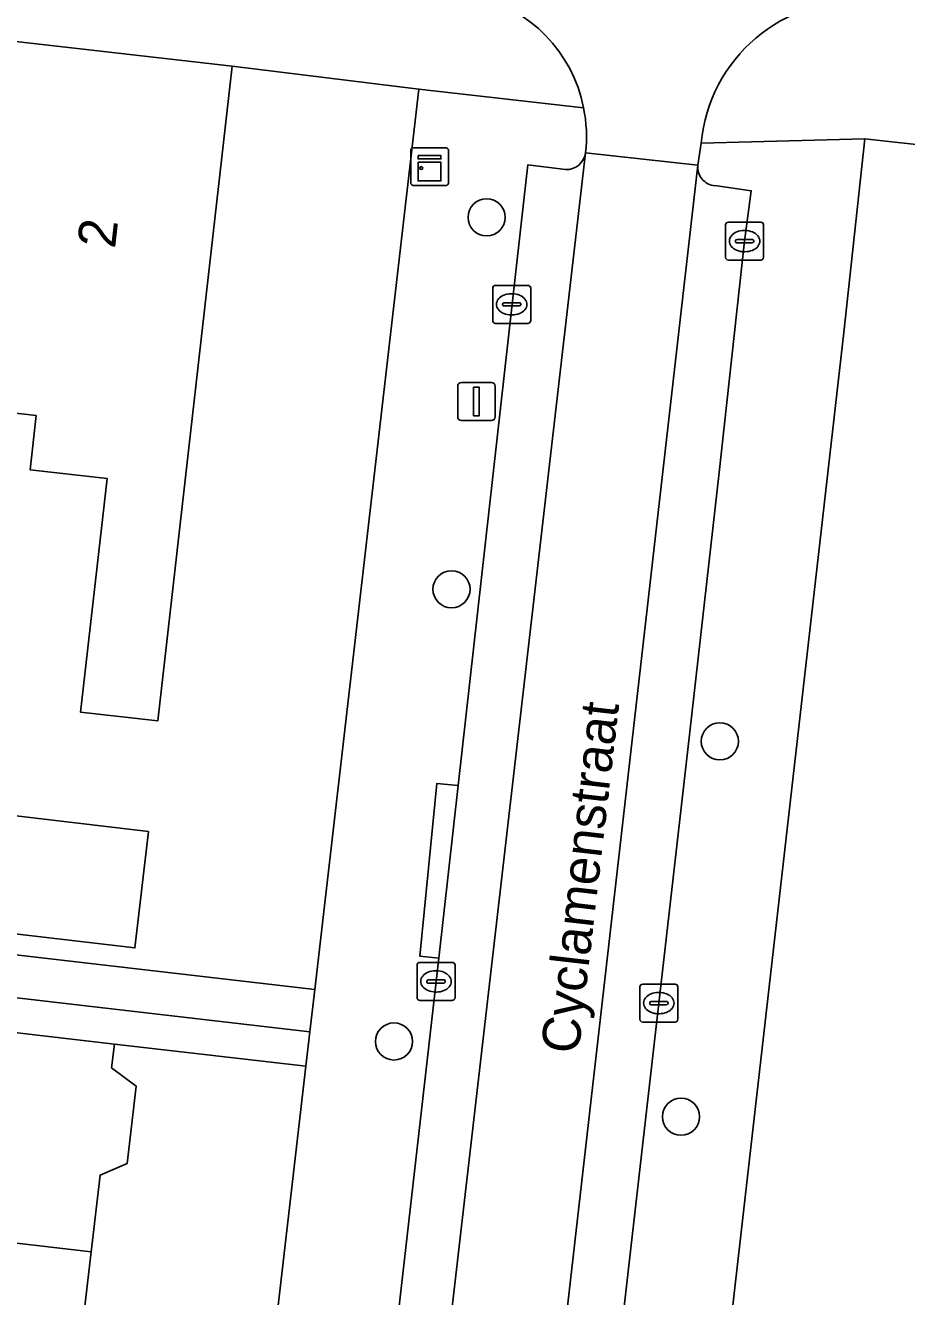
# Model space of a CAD drawing. Extents: x 161692 to 162379, y 380760 to 381678.
# Drawn here: x 162142.95 to 162166.16, y 381103.96 to 381137.43 of the extents above; entities that cross this region are included whole.
import ezdxf

# ---------------------------------------------------------------- set-up
doc = ezdxf.new("R2010")
doc.units = 0
for name, color, linetype in [('IMGEO_Boom', 7, 'Continuous'), ('IMGEO_Erf', 7, 'Continuous'), ('IMGEO_Kast', 7, 'Continuous'), ('IMGEO_Kolk', 7, 'Continuous'), ('IMGEO_Lichtmast', 7, 'Continuous'), ('IMGEO_Openbare_ruimte_label', 7, 'Continuous'), ('IMGEO_Pand', 7, 'Continuous'), ('IMGEO_Pand_nummerreeks', 7, 'Continuous'), ('IMGEO_Parkeervlak_open', 7, 'Continuous'), ('IMGEO_Rijbaan_lokaal_open', 7, 'Continuous'), ('IMGEO_Voetpad_open', 7, 'Continuous')]:
    doc.layers.add(name, color=color, linetype=linetype)

msp = doc.modelspace()

# ---------------------------------------------------------------- linework, layer by layer
at = {"layer": 'IMGEO_Boom'}
for centre in [(162155.095, 381132.374), (162154.17, 381122.581), (162161.239, 381118.576), (162152.655, 381110.673), (162160.215, 381108.691)]:
    msp.add_circle(centre, 0.489, dxfattribs=at)
at = {"layer": 'IMGEO_Erf'}
for points in [[(162104.656, 381117.359), (162150.568, 381112.043), (162153.313, 381135.753), (162148.389, 381136.356), (162146.43, 381119.113), (162144.4, 381119.344), (162145.098, 381125.495), (162143.069, 381125.726), (162143.231, 381127.155), (162140.973, 381127.411)], [(162171.096, 381133.774), (162165.058, 381134.446), (162164.506, 381129.345), (162160.903, 381097.801)], [(162140.287, 381068.173), (162145.42, 381067.579), (162150.334, 381110.022), (162145.291, 381110.606), (162145.217, 381109.977), (162145.862, 381109.497), (162145.625, 381107.462), (162144.913, 381107.155), (162144.677, 381105.13), (162144.441, 381103.106), (162145.069, 381102.638), (162144.826, 381100.55), (162144.087, 381100.231), (162144.046, 381099.885), (162144.006, 381099.539), (162144.651, 381099.059), (162144.403, 381096.929), (162143.679, 381096.788), (162143.437, 381094.71), (162143.194, 381092.63), (162143.859, 381092.136), (162143.6, 381089.916), (162142.846, 381089.59)]]:
    msp.add_lwpolyline(points, dxfattribs=at)
msp.add_lwpolyline([(162146.19, 381116.206), (162145.832, 381113.136), (162139.734, 381113.847), (162140.092, 381116.918)], close=True, dxfattribs=at)
at = {"layer": 'IMGEO_Kast'}
for p, q in [((162153.095, 381133.284), (162153.095, 381134.125)), ((162153.095, 381134.125), (162153.095, 381133.284)), ((162153.17, 381134.209), (162154.011, 381134.209)), ((162154.011, 381134.209), (162153.17, 381134.209)), ((162154.095, 381134.134), (162154.095, 381133.293)), ((162154.095, 381133.293), (162154.095, 381134.134)), ((162154.02, 381133.209), (162153.179, 381133.209)), ((162153.179, 381133.209), (162154.02, 381133.209))]:
    msp.add_line(p, q, dxfattribs=at)
for points in [[(162153.29, 381133.999), (162153.89, 381133.999), (162153.89, 381133.914), (162153.29, 381133.914), (162153.29, 381133.999)], [(162153.29, 381133.824), (162153.89, 381133.824), (162153.89, 381133.335), (162153.29, 381133.335), (162153.29, 381133.824)]]:
    msp.add_lwpolyline(points, dxfattribs=at)
msp.add_circle((162153.374, 381133.673), 0.0377, dxfattribs=at)
for centre, start, end in [((162153.173, 381134.131), 92.4484, 184.2845), ((162153.173, 381134.131), 92.4484, 184.2845), ((162154.017, 381134.131), 2.4484, 94.2845), ((162154.017, 381134.131), 2.4484, 94.2845), ((162153.173, 381133.287), 182.4484, 274.2845), ((162153.173, 381133.287), 182.4484, 274.2845), ((162154.017, 381133.287), 272.4484, 4.2845), ((162154.017, 381133.287), 272.4484, 4.2845)]:
    msp.add_arc(centre, 0.0779, start, end, dxfattribs=at)
at = {"layer": 'IMGEO_Kolk'}
for p, q in [((162161.465, 381132.248), (162162.317, 381132.248)), ((162161.39, 381131.322), (162161.39, 381132.174)), ((162161.878, 381132.028), (162161.903, 381132.028)), ((162162.391, 381132.174), (162162.391, 381131.322)), ((162161.649, 381131.742), (162161.649, 381131.754)), ((162162.087, 381131.705), (162161.689, 381131.705)), ((162161.692, 381131.791), (162162.09, 381131.791)), ((162162.133, 381131.754), (162162.133, 381131.742)), ((162162.317, 381131.248), (162161.465, 381131.248)), ((162161.901, 381131.468), (162161.876, 381131.468)), ((162155.331, 381130.583), (162156.183, 381130.583)), ((162155.256, 381129.657), (162155.256, 381130.509)), ((162155.744, 381130.363), (162155.769, 381130.363)), ((162156.257, 381130.509), (162156.257, 381129.657)), ((162155.515, 381130.077), (162155.515, 381130.089)), ((162155.953, 381130.04), (162155.555, 381130.04)), ((162155.558, 381130.126), (162155.956, 381130.126)), ((162155.999, 381130.089), (162155.999, 381130.077)), ((162156.183, 381129.583), (162155.331, 381129.583)), ((162155.767, 381129.803), (162155.742, 381129.803)), ((162153.262, 381111.828), (162153.262, 381112.68)), ((162153.337, 381112.754), (162154.189, 381112.754)), ((162153.75, 381112.534), (162153.775, 381112.534)), ((162154.263, 381112.68), (162154.263, 381111.828)), ((162153.521, 381112.248), (162153.521, 381112.26)), ((162153.959, 381112.211), (162153.561, 381112.211)), ((162153.564, 381112.297), (162153.962, 381112.297)), ((162154.005, 381112.26), (162154.005, 381112.248)), ((162159.207, 381112.183), (162160.059, 381112.183)), ((162153.773, 381111.974), (162153.748, 381111.974)), ((162159.132, 381111.257), (162159.132, 381112.109)), ((162159.62, 381111.963), (162159.645, 381111.963)), ((162160.133, 381112.109), (162160.133, 381111.257)), ((162154.189, 381111.754), (162153.337, 381111.754)), ((162159.391, 381111.677), (162159.391, 381111.689)), ((162159.829, 381111.64), (162159.431, 381111.64)), ((162159.434, 381111.726), (162159.832, 381111.726)), ((162159.875, 381111.689), (162159.875, 381111.677)), ((162160.059, 381111.183), (162159.207, 381111.183)), ((162159.643, 381111.403), (162159.618, 381111.403))]:
    msp.add_line(p, q, dxfattribs=at)
for points in [[(162161.465, 381132.248), (162162.317, 381132.248)], [(162161.39, 381131.322), (162161.39, 381132.174)], [(162162.391, 381132.174), (162162.391, 381131.322)], [(162162.317, 381131.248), (162161.465, 381131.248)], [(162155.331, 381130.583), (162156.183, 381130.583)], [(162155.256, 381129.657), (162155.256, 381130.509)], [(162156.257, 381130.509), (162156.257, 381129.657)], [(162156.183, 381129.583), (162155.331, 381129.583)], [(162153.262, 381111.828), (162153.262, 381112.68)], [(162153.337, 381112.754), (162154.189, 381112.754)], [(162154.263, 381112.68), (162154.263, 381111.828)], [(162159.207, 381112.183), (162160.059, 381112.183)], [(162159.132, 381111.257), (162159.132, 381112.109)], [(162160.133, 381112.109), (162160.133, 381111.257)], [(162154.189, 381111.754), (162153.337, 381111.754)], [(162160.059, 381111.183), (162159.207, 381111.183)]]:
    msp.add_lwpolyline(points, dxfattribs=at)
for centre, radius, start, end in [((162161.467, 381132.172), 0.0765, 91.552, 178.448), ((162161.467, 381132.172), 0.0765, 91.552, 178.448), ((162162.315, 381132.172), 0.0765, 1.552, 88.448), ((162162.315, 381132.172), 0.0765, 1.552, 88.448), ((162161.689, 381131.751), 0.0403, 85.8775, 175.7526), ((162161.686, 381131.741), 0.0366, 178.938, 274.7102), ((162162.09, 381131.748), 0.043, 264.8664, 352.4533), ((162162.094, 381131.753), 0.0386, 1.7309, 96.639), ((162161.467, 381131.324), 0.0765, 181.552, 268.448), ((162161.467, 381131.324), 0.0765, 181.552, 268.448), ((162162.315, 381131.324), 0.0765, 271.552, 358.448), ((162162.315, 381131.324), 0.0765, 271.552, 358.448), ((162155.333, 381130.507), 0.0765, 91.552, 178.448), ((162155.333, 381130.507), 0.0765, 91.552, 178.448), ((162156.181, 381130.507), 0.0765, 1.552, 88.448), ((162156.181, 381130.507), 0.0765, 1.552, 88.448), ((162155.555, 381130.086), 0.0403, 85.8775, 175.7526), ((162155.552, 381130.076), 0.0366, 178.938, 274.7102), ((162155.956, 381130.083), 0.043, 264.8664, 352.4533), ((162155.96, 381130.088), 0.0386, 1.7309, 96.639), ((162155.333, 381129.659), 0.0765, 181.552, 268.448), ((162155.333, 381129.659), 0.0765, 181.552, 268.448), ((162156.181, 381129.659), 0.0765, 271.552, 358.448), ((162156.181, 381129.659), 0.0765, 271.552, 358.448), ((162153.339, 381112.678), 0.0765, 91.552, 178.448), ((162153.339, 381112.678), 0.0765, 91.552, 178.448), ((162154.187, 381112.678), 0.0765, 1.552, 88.448), ((162154.187, 381112.678), 0.0765, 1.552, 88.448), ((162153.561, 381112.257), 0.0403, 85.8775, 175.7526), ((162153.558, 381112.247), 0.0366, 178.938, 274.7102), ((162153.962, 381112.254), 0.043, 264.8664, 352.4533), ((162153.966, 381112.259), 0.0386, 1.7309, 96.639), ((162159.209, 381112.107), 0.0765, 91.552, 178.448), ((162159.209, 381112.107), 0.0765, 91.552, 178.448), ((162160.057, 381112.107), 0.0765, 1.552, 88.448), ((162160.057, 381112.107), 0.0765, 1.552, 88.448), ((162153.339, 381111.83), 0.0765, 181.552, 268.448), ((162153.339, 381111.83), 0.0765, 181.552, 268.448), ((162154.187, 381111.83), 0.0765, 271.552, 358.448), ((162154.187, 381111.83), 0.0765, 271.552, 358.448), ((162159.431, 381111.686), 0.0403, 85.8775, 175.7526), ((162159.428, 381111.676), 0.0366, 178.938, 274.7102), ((162159.832, 381111.683), 0.043, 264.8664, 352.4533), ((162159.836, 381111.688), 0.0386, 1.7309, 96.639), ((162159.209, 381111.259), 0.0765, 181.552, 268.448), ((162159.209, 381111.259), 0.0765, 181.552, 268.448), ((162160.057, 381111.259), 0.0765, 271.552, 358.448), ((162160.057, 381111.259), 0.0765, 271.552, 358.448)]:
    msp.add_arc(centre, radius, start, end, dxfattribs=at)
for centre, major_axis, ratio, start_param, end_param in [((162161.877, 381131.748), (-0.387, 0.002), 0.722429, 4.712389, 7.853982), ((162161.902, 381131.748), (-0.39, 0.002), 0.717154, 1.570796, 4.712389), ((162155.743, 381130.083), (-0.387, 0.002), 0.722429, 4.712389, 7.853982), ((162155.768, 381130.083), (-0.39, 0.002), 0.717154, 1.570796, 4.712389), ((162153.749, 381112.254), (-0.387, 0.002), 0.722429, 4.712389, 7.853982), ((162153.774, 381112.254), (-0.39, 0.002), 0.717154, 1.570796, 4.712389), ((162159.619, 381111.683), (-0.387, 0.002), 0.722429, 4.712389, 7.853982), ((162159.644, 381111.683), (-0.39, 0.002), 0.717154, 1.570796, 4.712389)]:
    msp.add_ellipse(centre, major_axis=major_axis, ratio=ratio, start_param=start_param, end_param=end_param, dxfattribs=at)
at = {"layer": 'IMGEO_Lichtmast'}
for p, q in [((162154.333, 381127.125), (162154.333, 381127.925)), ((162154.333, 381127.925), (162154.333, 381127.125)), ((162154.433, 381128.025), (162155.223, 381128.025)), ((162155.223, 381128.025), (162154.433, 381128.025)), ((162155.323, 381127.925), (162155.323, 381127.125)), ((162155.323, 381127.125), (162155.323, 381127.925)), ((162155.223, 381127.025), (162154.433, 381127.025)), ((162154.433, 381127.025), (162155.223, 381127.025))]:
    msp.add_line(p, q, dxfattribs=at)
msp.add_lwpolyline([(162154.753, 381127.9), (162154.903, 381127.9), (162154.903, 381127.15), (162154.753, 381127.15), (162154.753, 381127.9)], dxfattribs=at)
for centre, start, end in [((162154.433, 381127.925), 90, 180), ((162154.433, 381127.925), 90, 180), ((162155.223, 381127.925), 0, 90), ((162155.223, 381127.925), 360, 90), ((162154.433, 381127.125), 180, 270), ((162154.433, 381127.125), 180, 270), ((162155.223, 381127.125), 270, 0), ((162155.223, 381127.125), 270, 0)]:
    msp.add_arc(centre, 0.1, start, end, dxfattribs=at)
at = {"layer": 'IMGEO_Pand'}
for points in [[(162140.973, 381127.411), (162143.231, 381127.155), (162143.069, 381125.726), (162145.098, 381125.495), (162144.4, 381119.344), (162146.43, 381119.113), (162148.389, 381136.356), (162142.069, 381137.074)], [(162146.19, 381116.206), (162140.092, 381116.918), (162139.734, 381113.847), (162145.832, 381113.136)], [(162145.862, 381109.497), (162145.217, 381109.977), (162145.291, 381110.606), (162140.325, 381111.185), (162136.865, 381111.589), (162133.859, 381111.929), (162133.856, 381111.905), (162133.39, 381108.347), (162133.186, 381106.474), (162136.227, 381106.118), (162144.677, 381105.13), (162144.913, 381107.155), (162145.625, 381107.462)], [(162144.677, 381105.13), (162136.227, 381106.118), (162135.616, 381100.871), (162144.046, 381099.885), (162144.087, 381100.231), (162144.826, 381100.55), (162145.069, 381102.638), (162144.441, 381103.106)]]:
    msp.add_lwpolyline(points, close=True, dxfattribs=at)
at = {"layer": 'IMGEO_Parkeervlak_open'}
for points in [[(162149.756, 381065.313), (162157.702, 381134.076)], [(162157.17, 381133.632), (162156.184, 381133.76), (162156.077, 381132.828), (162154.344, 381117.414), (162153.833, 381112.868), (162152.135, 381097.939), (162150.269, 381081.843), (162148.321, 381065.955), (162149.229, 381065.849)], [(162160.66, 381133.748), (162152.8, 381064.956)], [(162153.418, 381065.31), (162154.312, 381065.207), (162155.796, 381077.901), (162158.367, 381100.621), (162160.396, 381118.363), (162161.223, 381125.654), (162161.89, 381131.748), (162162.069, 381133.076), (162161.11, 381133.209)]]:
    msp.add_lwpolyline(points, dxfattribs=at)
for centre, radius, start, end in [((162157.192, 381134.146), 0.514, 267.5064, 352.1895), ((162161.146, 381133.696), 0.489, 173.9431, 265.7725)]:
    msp.add_arc(centre, radius, start, end, dxfattribs=at)
at = {"layer": 'IMGEO_Rijbaan_lokaal_open'}
msp.add_lwpolyline([(162157.702, 381134.076), (162160.66, 381133.748), (162160.751, 381134.327)], dxfattribs=at)
msp.add_lwpolyline([(162160.66, 381133.748), (162157.702, 381134.076), (162149.756, 381065.313), (162152.8, 381064.956)], close=True, dxfattribs=at)
for centre, radius, start, end in [((162153.918, 381134.508), 3.808, 11.3713, 76.838), ((162164.846, 381133.959), 4.111, 85.865, 174.8588), ((162153.939, 381134.506), 3.787, 353.4744, 11.4626)]:
    msp.add_arc(centre, radius, start, end, dxfattribs=at)
at = {"layer": 'IMGEO_Voetpad_open'}
for points in [[(162142.069, 381137.074), (162148.389, 381136.356), (162153.313, 381135.753), (162157.651, 381135.259)], [(162157.651, 381135.259), (162153.313, 381135.753), (162150.568, 381112.043), (162150.439, 381110.931), (162150.334, 381110.022), (162145.42, 381067.579), (162145.245, 381066.064), (162142.43, 381041.751), (162142.287, 381040.513), (162140.67, 381026.549), (162139.37, 381016.118), (162139.218, 381014.896), (162137.362, 381000), (162136.33, 380990.718), (162136.201, 380989.562), (162133.45, 380964.827), (162133.292, 380963.402), (162133.289, 380963.379), (162132.879, 380959.696), (162131.228, 380944.847)], [(162149.233, 380991.854), (162149.082, 380992.2), (162149.047, 380994.003), (162149.732, 381000), (162157.02, 381063.805), (162157.194, 381065.33), (162160.798, 381096.879), (162160.903, 381097.801), (162164.506, 381129.345), (162165.058, 381134.446), (162160.751, 381134.327), (162160.66, 381133.748)], [(162160.751, 381134.327), (162165.058, 381134.446), (162171.096, 381133.774), (162185.673, 381132.116), (162186.67, 381132.042), (162191.795, 381131.459), (162196.958, 381130.871), (162202.113, 381130.285), (162202.676, 381130.218), (162206.35, 381129.78), (162219.154, 381128.335), (162223.239, 381127.491)], [(162149.229, 381065.849), (162148.321, 381065.955), (162150.269, 381081.843), (162152.135, 381097.939), (162153.833, 381112.868), (162153.337, 381112.917), (162153.787, 381117.469), (162154.344, 381117.414), (162156.077, 381132.828), (162156.184, 381133.76), (162157.17, 381133.632)], [(162161.11, 381133.209), (162162.069, 381133.076), (162161.89, 381131.748), (162161.223, 381125.654), (162160.396, 381118.363), (162158.367, 381100.621), (162155.796, 381077.901), (162154.312, 381065.207), (162153.418, 381065.31)]]:
    msp.add_lwpolyline(points, dxfattribs=at)
for points in [[(162104.656, 381117.359), (162102.759, 381117.558), (162102.661, 381116.71), (162102.633, 381116.465), (162104.527, 381116.246), (162108.158, 381115.826), (162123.177, 381114.087), (162150.439, 381110.931), (162150.568, 381112.043)], [(162153.833, 381112.868), (162154.344, 381117.414), (162153.787, 381117.469), (162153.337, 381112.917)], [(162123.177, 381114.087), (162122.47, 381108.579), (162119.678, 381086.815), (162120.872, 381086.689), (162124.236, 381112.916), (162133.856, 381111.905), (162133.859, 381111.929), (162136.865, 381111.589), (162140.325, 381111.185), (162145.291, 381110.606), (162150.334, 381110.022), (162150.439, 381110.931)]]:
    msp.add_lwpolyline(points, close=True, dxfattribs=at)
for centre, radius, start, end in [((162153.918, 381134.508), 3.808, 11.3713, 76.838), ((162164.846, 381133.959), 4.111, 85.865, 174.8588), ((162153.939, 381134.506), 3.787, 353.4744, 11.4626), ((162157.192, 381134.146), 0.514, 267.5064, 352.1895), ((162161.146, 381133.696), 0.489, 173.9431, 265.7725)]:
    msp.add_arc(centre, radius, start, end, dxfattribs=at)

# ---------------------------------------------------------------- texts
at = {"layer": 'IMGEO_Openbare_ruimte_label'}
msp.add_text('Cyclamenstraat', height=1, rotation=83.394, dxfattribs=at).set_placement((162157.515, 381110.321))
at = {"layer": 'IMGEO_Pand_nummerreeks'}
msp.add_text('2', height=1, rotation=83.5183, dxfattribs=at).set_placement((162145.305, 381131.534))

doc.saveas('drawing.dxf')
